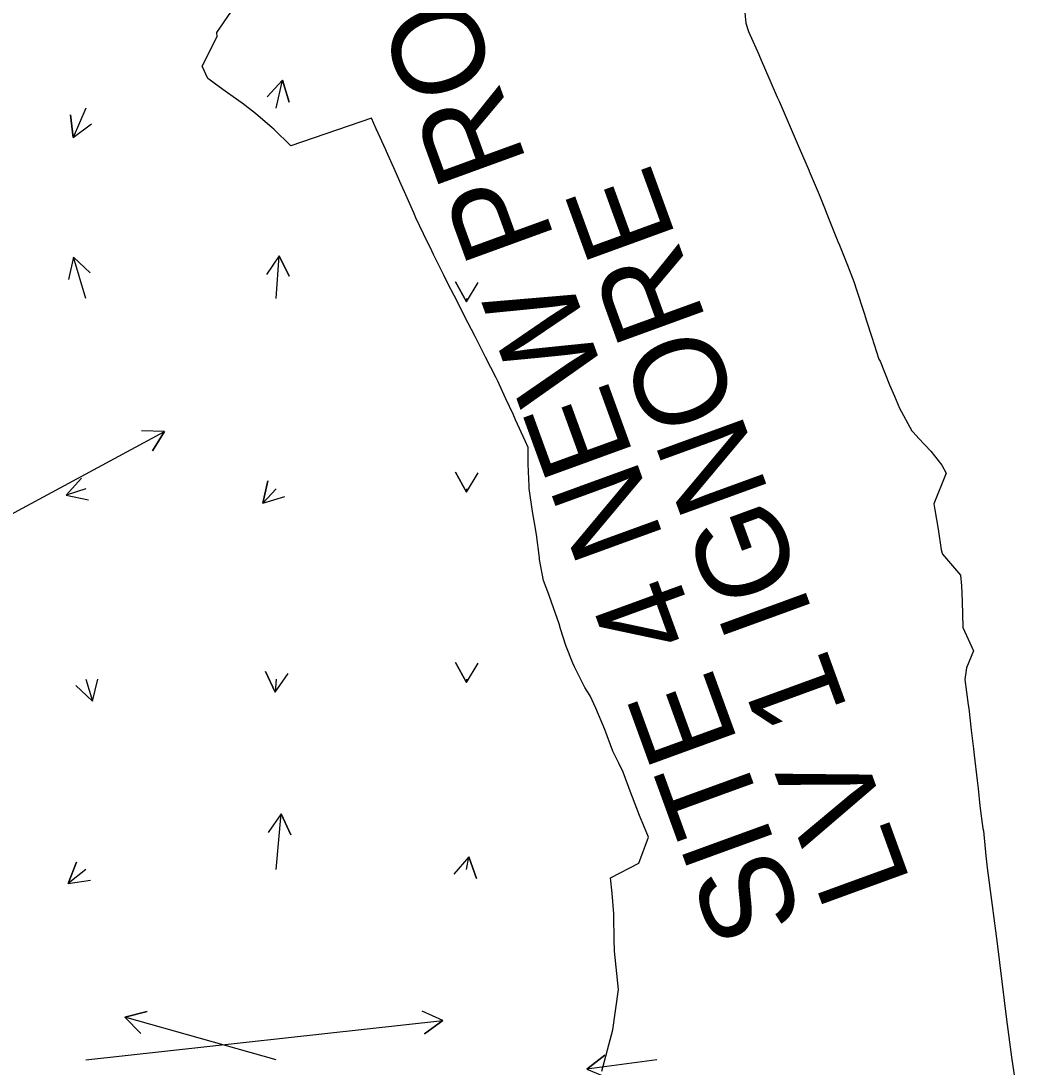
# Model space of a CAD drawing. Extents: x 954385 to 988206, y 1868364 to 1924553.
# Drawn here: x 957890 to 958151.8, y 1919767 to 1920041.8 of the extents above; entities that cross this region are included whole.
import ezdxf

# ---------------------------------------------------------------- set-up
doc = ezdxf.new("R2010")
doc.units = 0
for name, color, linetype in [('14', 7, 'Continuous'), ('24', 7, 'Continuous'), ('26', 7, 'Continuous')]:
    doc.layers.add(name, color=color, linetype=linetype)

msp = doc.modelspace()

# ---------------------------------------------------------------- linework, layer by layer
at = {"layer": '24'}
for points in [[(958042.73, 1919765.91), (958045.59, 1919776.8), (958047.12, 1919787.39), (958046.05, 1919797.4), (958045.93, 1919800.54), (958045.86, 1919806.65), (958045.85, 1919807.22), (958045.45, 1919812.69), (958044.98, 1919816.74), (958052.42, 1919820.55), (958054.94, 1919827.4), (958054.32, 1919828.88), (958052.58, 1919833.05), (958050.79, 1919837.87), (958050.45, 1919838.75), (958048.28, 1919844.43), (958047.14, 1919846.8), (958045.59, 1919849.96), (958043.47, 1919855.64), (958043.45, 1919855.7), (958041.12, 1919861.24), (958039.63, 1919864.53), (958038.27, 1919866.68), (958035.53, 1919872.14), (958035.12, 1919873.13), (958033.23, 1919877.73), (958031.88, 1919882.1), (958031.45, 1919883.47), (958029.46, 1919889.15), (958028.76, 1919891.1), (958027.4, 1919894.8), (958026.64, 1919898.51), (958026.35, 1919900.33), (958026.3, 1919900.78), (958025.53, 1919906.89), (958024.97, 1919909.95), (958024.45, 1919912.9), (958023.63, 1919919.02), (958023.57, 1919919.59), (958023.31, 1919925.34), (958023.37, 1919929.73), (958022.55, 1919931.52), (958020.04, 1919937.05), (958019.38, 1919938.48), (958017.49, 1919942.56), (958015.34, 1919947.2), (958014.92, 1919948.05), (958012.14, 1919953.45), (958010.97, 1919955.77), (958009.4, 1919958.87), (958006.65, 1919964.28), (958006.63, 1919964.33), (958003.89, 1919969.67), (958002.24, 1919972.86), (958001.15, 1919975.06), (957998.48, 1919980.49), (957998.01, 1919981.45), (957995.81, 1919985.91), (957993.86, 1919990.06), (957993.28, 1919991.39), (957990.84, 1919996.91), (957989.99, 1919998.8), (957988.39, 1920002.43), (957986.11, 1920007.54), (957985.93, 1920007.94), (957983.43, 1920013.44), (957982.17, 1920016.26), (957960.96, 1920009.01), (957956.51, 1920013.38), (957956.07, 1920013.76), (957951.7, 1920017.52), (957948.23, 1920020.19), (957946.44, 1920021.4), (957943.75, 1920023.33), (957941.15, 1920025.22), (957939.79, 1920026.21), (957939.18, 1920026.65), (957937.66, 1920029.97), (957941.6, 1920037.71), (957941.54, 1920038.73), (957948.92, 1920049.54)], [(958080.07, 1920045.88), (958080.54, 1920041.25), (958081.22, 1920039.05), (958083.93, 1920032.95), (958084.57, 1920031.49), (958086.6, 1920026.84), (958088.8, 1920021.81), (958089.27, 1920020.73), (958091.93, 1920014.62), (958093, 1920012.13), (958094.57, 1920008.49), (958097.14, 1920002.42), (958097.17, 1920002.36), (958099.78, 1919996.22), (958101.25, 1919992.69), (958102.27, 1919990.04), (958104.74, 1919983.84), (958105.13, 1919982.88), (958107.22, 1919977.66), (958109.01, 1919973.06), (958109.55, 1919971.41), (958111.61, 1919965.06), (958112.27, 1919963.01), (958113.65, 1919958.71), (958115.49, 1919952.95), (958115.87, 1919952.43), (958118.33, 1919946.23), (958119.62, 1919943.22), (958120.95, 1919940.09), (958124.18, 1919934.15), (958124.54, 1919933.75), (958126.04, 1919932.13), (958129.12, 1919928.76), (958132.03, 1919925.09), (958133.2, 1919923.05), (958129.93, 1919914.97), (958130.24, 1919913.39), (958131.07, 1919908.33), (958131.89, 1919902.85), (958132.25, 1919901.73), (958136.97, 1919896.19), (958137.2, 1919893.43), (958137.36, 1919889.34), (958137.6, 1919882.55), (958137.6, 1919882.48), (958140.34, 1919876.33), (958138.55, 1919871.88), (958138.11, 1919868.82), (958138.97, 1919862.19), (958139.11, 1919861.15), (958139.73, 1919855.53), (958140.33, 1919850.63), (958140.54, 1919848.9), (958141.31, 1919842.28), (958141.55, 1919840.14), (958142.04, 1919835.65), (958142.8, 1919829.69), (958142.96, 1919829.08), (958143.57, 1919822.45), (958143.96, 1919819.37), (958145.24, 1919809.41), (958146.56, 1919799.46), (958147.84, 1919789.5), (958149.06, 1919779.52), (958150.37, 1919769.57), (958151.82, 1919759.64)]]:
    msp.add_lwpolyline(points, dxfattribs=at)
at = {"layer": '26'}
for points in [[(957957.13, 1920018.93), (957958.82, 1920026.21), (957960.57, 1920020.47), (957958.82, 1920026.21), (957954.72, 1920021.83)], [(957907.13, 1920018.93), (957903.79, 1920011.16), (957903.09, 1920017.12), (957903.79, 1920011.16), (957908.6, 1920014.75)], [(957907.13, 1919968.93), (957903.89, 1919979.74), (957908.25, 1919975.63), (957903.89, 1919979.74), (957902.51, 1919973.9)], [(957957.13, 1919968.93), (957957.95, 1919980.13), (957960.57, 1919974.73), (957957.95, 1919980.13), (957954.58, 1919975.17)], [(958007.13, 1919968.93), (958007.11, 1919967.98), (958004.22, 1919973.24), (958007.11, 1919967.98), (958010.22, 1919973.12)], [(957807.13, 1919868.93), (957927.77, 1919933.94), (957924.62, 1919928.84), (957927.77, 1919933.94), (957921.77, 1919934.12)], [(957907.13, 1919918.93), (957901.93, 1919917.27), (957905.97, 1919921.71), (957901.93, 1919917.27), (957907.79, 1919915.99)], [(957957.13, 1919918.93), (957953.63, 1919915.15), (957954.96, 1919921), (957953.63, 1919915.15), (957959.36, 1919916.92)], [(958007.13, 1919918.93), (958007.11, 1919917.98), (958004.22, 1919923.24), (958007.11, 1919917.98), (958010.22, 1919923.12)], [(958007.13, 1919868.93), (958007.11, 1919867.98), (958004.22, 1919873.24), (958007.11, 1919867.98), (958010.22, 1919873.12)], [(957907.13, 1919868.93), (957908.9, 1919863.09), (957904.52, 1919867.19), (957908.9, 1919863.09), (957910.26, 1919868.93)], [(957957.13, 1919868.93), (957956.82, 1919865.5), (957954.3, 1919870.95), (957956.82, 1919865.5), (957960.28, 1919870.41)], [(957957.13, 1919818.93), (957958.48, 1919833.48), (957960.99, 1919828.03), (957958.48, 1919833.48), (957955.01, 1919828.59)], [(958007.13, 1919818.93), (958007.75, 1919822.23), (958009.74, 1919816.57), (958007.75, 1919822.23), (958003.84, 1919817.67)], [(957907.13, 1919818.93), (957902.44, 1919815.22), (957904.65, 1919820.79), (957902.44, 1919815.22), (957908.37, 1919816.09)], [(957907.13, 1919768.93), (958000.95, 1919779.24), (957996.11, 1919775.69), (958000.95, 1919779.24), (957995.46, 1919781.66)], [(957957.13, 1919768.93), (957917.39, 1919780.11), (957923.21, 1919781.59), (957917.39, 1919780.11), (957921.58, 1919775.81)], [(958057.13, 1919768.93), (958038.76, 1919766.47), (958043.51, 1919770.13), (958038.76, 1919766.47), (958044.3, 1919764.18)]]:
    msp.add_lwpolyline(points, dxfattribs=at)

# ---------------------------------------------------------------- texts
at = {"layer": '14'}
for s, p in [('SITE 4 NEW PROFILE MOT', (958095.78, 1919805.25)), ('LV 1 IGNORE', (958124.01, 1919815.53))]:
    msp.add_text(s, height=24, rotation=110, dxfattribs=at).set_placement(p)

doc.saveas('drawing.dxf')
